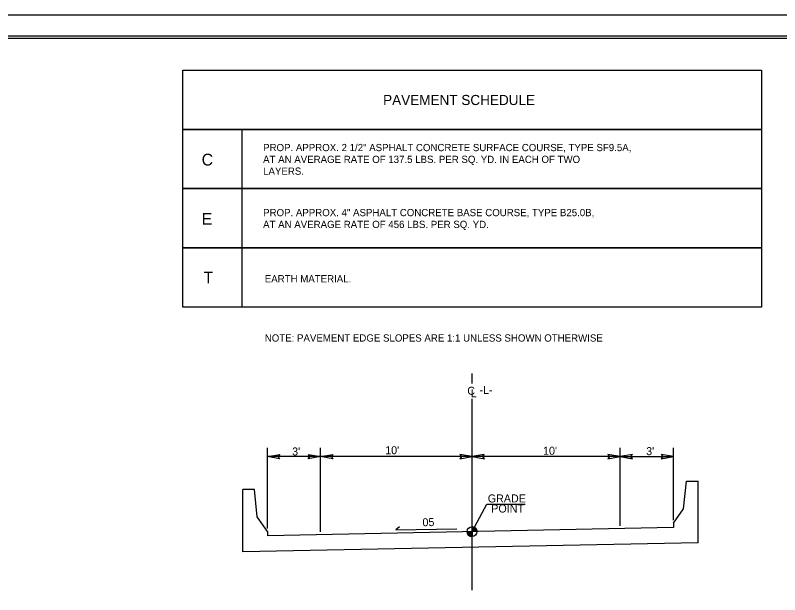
# Model space of a CAD drawing. Extents: x 106738.7 to 106779.9, y 105993.5 to 106034.9.
# Drawn here: x 106747.14 to 106763.66, y 106022.37 to 106034.88 of the extents above; entities that cross this region are included whole.
import ezdxf

# ---------------------------------------------------------------- set-up
doc = ezdxf.new("R2010")
doc.units = 0
for name, color, linetype in [('Old_Level_1', 7, 'Continuous'), ('Old_Level_11', 7, 'Continuous'), ('Old_Level_2', 7, 'Continuous'), ('Old_Level_21', 7, 'Continuous'), ('Prop Pavement Schedule Description CELL', 7, 'Continuous'), ('Sheet Cutting Line CELL', 7, 'Continuous'), ('Sheet Plot Border Inside CELL', 7, 'Continuous'), ('Sheet Plot Border Outside CELL', 7, 'Continuous'), ('Sheet Typical CELL', 7, 'Continuous')]:
    doc.layers.add(name, color=color, linetype=linetype)

msp = doc.modelspace()

# ---------------------------------------------------------------- linework, layer by layer
at = {"layer": 'Old_Level_1'}
for p, q in [((106757.015, 106023.729), (106757.333, 106024.318)), ((106757.333, 106024.318), (106758.159, 106024.318)), ((106757.015, 106023.729), (106757.015, 106023.835)), ((106756.909, 106023.729), (106757.015, 106023.729)), ((106757.122, 106023.729), (106757.015, 106023.729)), ((106757.015, 106023.622), (106757.015, 106023.729)), ((106757.015, 106023.729), (106757.015, 106023.622))]:
    msp.add_line(p, q, dxfattribs=at)
for points in [[(106755.446, 106023.832), (106755.367, 106023.764), (106756.687, 106023.79)], [(106757.016, 106023.835), (106757.016, 106023.835), (106757.016, 106023.729)], [(106757.019, 106023.835), (106757.019, 106023.729)], [(106757.021, 106023.835), (106757.021, 106023.729)], [(106757.023, 106023.835), (106757.023, 106023.729)], [(106757.025, 106023.834), (106757.025, 106023.729)], [(106757.027, 106023.834), (106757.027, 106023.729)], [(106757.029, 106023.834), (106757.029, 106023.729)], [(106757.031, 106023.834), (106757.031, 106023.729)], [(106757.033, 106023.834), (106757.033, 106023.729)], [(106757.036, 106023.833), (106757.036, 106023.729)], [(106757.038, 106023.833), (106757.038, 106023.729)], [(106757.04, 106023.832), (106757.04, 106023.729)], [(106757.042, 106023.832), (106757.042, 106023.729)], [(106757.044, 106023.831), (106757.044, 106023.729)], [(106757.046, 106023.83), (106757.046, 106023.729)], [(106757.048, 106023.83), (106757.048, 106023.729)], [(106757.05, 106023.829), (106757.05, 106023.729)], [(106757.053, 106023.828), (106757.053, 106023.729)], [(106757.055, 106023.827), (106757.055, 106023.729)], [(106757.057, 106023.826), (106757.057, 106023.729)], [(106757.059, 106023.826), (106757.059, 106023.729)], [(106757.061, 106023.825), (106757.061, 106023.729)], [(106757.063, 106023.824), (106757.063, 106023.729)], [(106757.065, 106023.822), (106757.065, 106023.729)], [(106757.067, 106023.821), (106757.067, 106023.729)], [(106757.07, 106023.82), (106757.07, 106023.729)], [(106757.072, 106023.819), (106757.072, 106023.729)], [(106757.074, 106023.817), (106757.074, 106023.729)], [(106757.076, 106023.816), (106757.076, 106023.729)], [(106757.078, 106023.814), (106757.078, 106023.729)], [(106757.08, 106023.813), (106757.08, 106023.729)], [(106757.082, 106023.811), (106757.082, 106023.729)], [(106757.084, 106023.809), (106757.084, 106023.729)], [(106757.087, 106023.808), (106757.087, 106023.729)], [(106757.089, 106023.806), (106757.089, 106023.729)], [(106757.091, 106023.803), (106757.091, 106023.729)], [(106757.093, 106023.801), (106757.093, 106023.729)], [(106757.095, 106023.799), (106757.095, 106023.729)], [(106757.097, 106023.796), (106757.097, 106023.729)], [(106757.099, 106023.794), (106757.099, 106023.729)], [(106757.101, 106023.791), (106757.101, 106023.729)], [(106757.104, 106023.788), (106757.104, 106023.729)], [(106757.106, 106023.785), (106757.106, 106023.729)], [(106757.108, 106023.781), (106757.108, 106023.729)], [(106757.11, 106023.777), (106757.11, 106023.729)], [(106756.91, 106023.729), (106756.91, 106023.717)], [(106756.912, 106023.729), (106756.912, 106023.705)], [(106756.914, 106023.729), (106756.914, 106023.697)], [(106756.916, 106023.729), (106756.916, 106023.691)], [(106756.918, 106023.729), (106756.918, 106023.686)], [(106756.92, 106023.729), (106756.92, 106023.681)], [(106756.922, 106023.729), (106756.922, 106023.677)], [(106756.925, 106023.729), (106756.925, 106023.673)], [(106756.927, 106023.729), (106756.927, 106023.67)], [(106756.929, 106023.729), (106756.929, 106023.667)], [(106756.931, 106023.729), (106756.931, 106023.664)], [(106756.933, 106023.729), (106756.933, 106023.662)], [(106756.935, 106023.729), (106756.935, 106023.659)], [(106756.937, 106023.729), (106756.937, 106023.657)], [(106756.939, 106023.729), (106756.939, 106023.654)], [(106756.942, 106023.729), (106756.942, 106023.652)], [(106756.944, 106023.729), (106756.944, 106023.65)], [(106756.946, 106023.729), (106756.946, 106023.648)], [(106756.948, 106023.729), (106756.948, 106023.646)], [(106756.95, 106023.729), (106756.95, 106023.645)], [(106756.952, 106023.729), (106756.952, 106023.643)], [(106756.954, 106023.729), (106756.954, 106023.642)], [(106756.956, 106023.729), (106756.956, 106023.64)], [(106756.959, 106023.729), (106756.959, 106023.639)], [(106756.961, 106023.729), (106756.961, 106023.637)], [(106756.963, 106023.729), (106756.963, 106023.636)], [(106756.965, 106023.729), (106756.965, 106023.635)], [(106756.967, 106023.729), (106756.967, 106023.634)], [(106756.969, 106023.729), (106756.969, 106023.633)], [(106756.971, 106023.729), (106756.971, 106023.632)], [(106756.973, 106023.729), (106756.973, 106023.631)], [(106756.976, 106023.729), (106756.976, 106023.63)], [(106756.978, 106023.729), (106756.978, 106023.629)], [(106756.98, 106023.729), (106756.98, 106023.628)], [(106756.982, 106023.729), (106756.982, 106023.628)], [(106756.984, 106023.729), (106756.984, 106023.627)], [(106756.986, 106023.729), (106756.986, 106023.627)], [(106756.988, 106023.729), (106756.988, 106023.626)], [(106756.99, 106023.729), (106756.99, 106023.625)], [(106756.993, 106023.729), (106756.993, 106023.625)], [(106756.995, 106023.729), (106756.995, 106023.624)], [(106756.997, 106023.729), (106756.997, 106023.624)], [(106756.999, 106023.729), (106756.999, 106023.624)], [(106757.001, 106023.729), (106757.001, 106023.623)], [(106757.003, 106023.729), (106757.003, 106023.623)], [(106757.005, 106023.729), (106757.005, 106023.623)], [(106757.008, 106023.729), (106757.007, 106023.623)], [(106757.01, 106023.729), (106757.01, 106023.623)], [(106757.012, 106023.729), (106757.012, 106023.622)], [(106757.014, 106023.729), (106757.014, 106023.622), (106757.014, 106023.622)], [(106757.112, 106023.773), (106757.112, 106023.729)], [(106757.114, 106023.768), (106757.114, 106023.729)], [(106757.116, 106023.762), (106757.116, 106023.729)], [(106757.118, 106023.755), (106757.118, 106023.729)], [(106757.121, 106023.744), (106757.121, 106023.729)]]:
    msp.add_lwpolyline(points, dxfattribs=at)
msp.add_circle((106757.015, 106023.729), 0.106, dxfattribs=at)
for start, end in [(359.9905, 89.9905), (179.9905, 269.9905)]:
    msp.add_arc((106757.015, 106023.729), 0.106, start, end, dxfattribs=at)
at = {"layer": 'Old_Level_11'}
for p, q in [((106757.016, 106026.928), (106757.016, 106027.144)), ((106757.016, 106026.284), (106757.016, 106026.597)), ((106757.016, 106022.463), (106757.016, 106026.284)), ((106752.592, 106023.796), (106752.592, 106025.538)), ((106753.742, 106023.726), (106753.742, 106025.538)), ((106760.217, 106023.855), (106760.217, 106025.538)), ((106761.367, 106023.972), (106761.367, 106025.538)), ((106753.742, 106025.35), (106752.592, 106025.35)), ((106760.217, 106025.35), (106753.742, 106025.35)), ((106760.217, 106025.35), (106761.367, 106025.35))]:
    msp.add_line(p, q, dxfattribs=at)
for points in [[(106752.856, 106025.304), (106752.592, 106025.35), (106752.858, 106025.397), (106752.824, 106025.35)], [(106753.478, 106025.395), (106753.742, 106025.35), (106753.476, 106025.303), (106753.51, 106025.35)], [(106754.007, 106025.304), (106753.742, 106025.35), (106754.008, 106025.397), (106753.974, 106025.35)], [(106756.751, 106025.304), (106757.016, 106025.35), (106756.75, 106025.397), (106756.784, 106025.35)], [(106757.28, 106025.395), (106757.016, 106025.35), (106757.282, 106025.303), (106757.248, 106025.35)], [(106759.952, 106025.304), (106760.217, 106025.35), (106759.951, 106025.397), (106759.984, 106025.35)], [(106760.481, 106025.395), (106760.217, 106025.35), (106760.482, 106025.303), (106760.449, 106025.35)], [(106761.103, 106025.304), (106761.367, 106025.35), (106761.101, 106025.397), (106761.135, 106025.35)]]:
    msp.add_lwpolyline(points, close=True, dxfattribs=at)
at = {"layer": 'Old_Level_2'}
for p, q in [((106761.586, 106024.222), (106761.648, 106024.816)), ((106761.648, 106024.816), (106761.898, 106024.816)), ((106761.898, 106023.489), (106761.898, 106024.816)), ((106752.061, 106023.292), (106752.061, 106024.64)), ((106752.311, 106024.64), (106752.061, 106024.64)), ((106752.373, 106024.046), (106752.311, 106024.64)), ((106761.367, 106023.909), (106761.586, 106024.222)), ((106752.592, 106023.734), (106752.373, 106024.046)), ((106761.367, 106023.816), (106752.592, 106023.64)), ((106761.367, 106023.909), (106761.367, 106023.816)), ((106752.592, 106023.734), (106752.592, 106023.64)), ((106761.898, 106023.489), (106752.061, 106023.292))]:
    msp.add_line(p, q, dxfattribs=at)
at = {"layer": 'Prop Pavement Schedule Description CELL'}
for p, q in [((106750.766, 106032.415), (106750.766, 106033.694)), ((106750.766, 106033.694), (106763.266, 106033.694)), ((106763.266, 106033.694), (106763.266, 106032.415)), ((106763.266, 106032.415), (106750.766, 106032.415))]:
    msp.add_line(p, q, dxfattribs=at)
for points in [[(106752.044, 106031.137), (106750.766, 106031.137), (106750.766, 106032.415), (106763.266, 106032.415), (106763.266, 106031.137), (106752.044, 106031.137), (106752.044, 106032.415)], [(106752.044, 106029.858), (106750.766, 106029.858), (106750.766, 106031.137), (106763.266, 106031.137), (106763.266, 106029.858), (106752.044, 106029.858), (106752.044, 106031.137)], [(106752.045, 106028.579), (106750.766, 106028.579), (106750.766, 106029.858), (106763.269, 106029.858), (106763.269, 106028.579), (106752.045, 106028.579), (106752.045, 106029.858)]]:
    msp.add_lwpolyline(points, dxfattribs=at)
at = {"layer": 'Sheet Cutting Line CELL'}
msp.add_line((106772.356, 106034.882), (106738.676, 106034.882), dxfattribs=at)
at = {"layer": 'Sheet Plot Border Inside CELL'}
msp.add_lwpolyline([(106772.266, 106034.433), (106738.936, 106034.433), (106738.936, 106013.331), (106772.266, 106013.331)], close=True, dxfattribs=at)
at = {"layer": 'Sheet Plot Border Outside CELL'}
msp.add_lwpolyline([(106772.356, 106034.882), (106738.676, 106034.882), (106738.676, 106012.882), (106772.356, 106012.882)], close=True, dxfattribs=at)
at = {"layer": 'Sheet Typical CELL'}
msp.add_lwpolyline([(106772.016, 106034.382), (106742.016, 106034.382), (106742.016, 106013.382), (106772.016, 106013.382)], close=True, dxfattribs=at)

# ---------------------------------------------------------------- texts
at = {"layer": 'Old_Level_1'}
for s, height, rotation, p in [('C', 0.173, 360, (106756.912, 106026.684)), ('L', 0.173, 360, (106756.987, 106026.632)), ('-L-', 0.1729, 360, (106757.174, 106026.702)), ('GRADE ', 0.1729, 360, (106757.355, 106024.358)), ('POINT', 0.1729, 360, (106757.43, 106024.141)), ('05', 0.1729, 1.1122, (106755.945, 106023.843))]:
    msp.add_text(s, height=height, rotation=rotation, dxfattribs=at).set_placement(p)
at = {"layer": 'Old_Level_11'}
for s, rotation, p in [("3'", 0, (106753.127, 106025.373)), ("10'", 360, (106755.138, 106025.4)), ("10'", 360, (106758.549, 106025.389)), ("3'", 360, (106760.777, 106025.38))]:
    msp.add_text(s, height=0.1729, rotation=rotation, dxfattribs=at).set_placement(p)
at = {"layer": 'Old_Level_21'}
for s, height, rotation, p in [('PAVEMENT SCHEDULE', 0.21875, 360, (106755.093, 106032.943)), ('NOTE: PAVEMENT EDGE SLOPES ARE 1:1 UNLESS SHOWN OTHERWISE', 0.15628, 0, (106752.536, 106027.833))]:
    msp.add_text(s, height=height, rotation=rotation, dxfattribs=at).set_placement(p)
at = {"layer": 'Prop Pavement Schedule Description CELL'}
for s, height, p in [('PROP. APPROX. 2 1/2" ASPHALT CONCRETE SURFACE COURSE, TYPE SF9.5A, ', 0.15625, (106752.5, 106031.947)), ('C ', 0.2552, (106751.172, 106031.637)), ('AT AN AVERAGE RATE OF 137.5 LBS. PER SQ. YD. IN EACH OF TWO ', 0.15625, (106752.5, 106031.692)), ('LAYERS.', 0.1562, (106752.5, 106031.437)), ('E ', 0.2552, (106751.172, 106030.358)), ('PROP. APPROX. 4" ASPHALT CONCRETE BASE COURSE, TYPE B25.0B,', 0.15625, (106752.5, 106030.542)), ('AT AN AVERAGE RATE OF 456 LBS. PER SQ. YD.', 0.15625, (106752.5, 106030.287)), ('T ', 0.2501, (106751.214, 106029.091)), ('EARTH MATERIAL.', 0.15628, (106752.536, 106029.112))]:
    msp.add_text(s, height=height, dxfattribs=at).set_placement(p)

doc.saveas('drawing.dxf')
